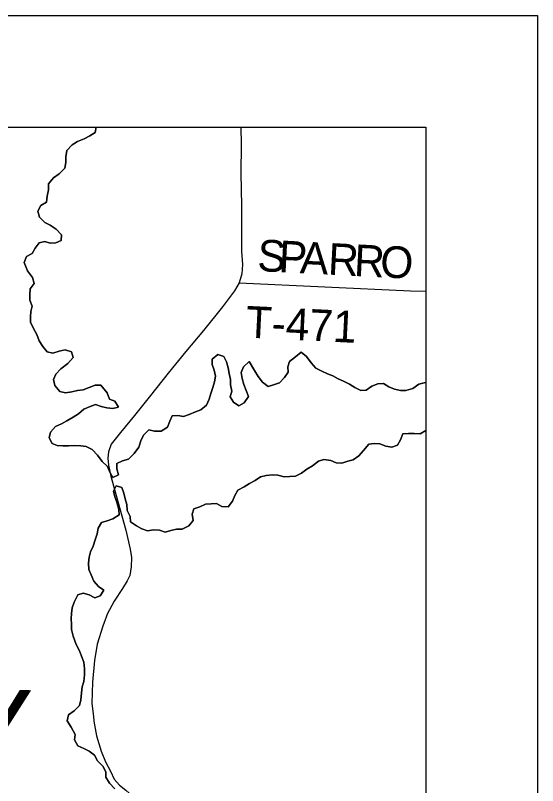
# Model space of a CAD drawing. Extents: x -22 to 431, y -18 to 160.
# Drawn here: x 331.059 to 331.995, y 158.739 to 160.12 of the extents above; entities that cross this region are included whole.
import ezdxf

# ---------------------------------------------------------------- set-up
doc = ezdxf.new("R2010")
doc.units = 0
for name, color, linetype in [('GM_X_City_Street_Text', 7, 'Continuous'), ('GM_X_County_ROW', 7, 'Continuous'), ('GM_X_Minor_River_Text', 7, 'Continuous'), ('GM_X_Section', 7, 'Continuous'), ('GM_X_Township_Subdivision', 7, 'Continuous'), ('GM_X_Unincorporated_Text', 7, 'Continuous')]:
    doc.layers.add(name, color=color, linetype=linetype)

msp = doc.modelspace()

# ---------------------------------------------------------------- linework, layer by layer
at = {"layer": 'GM_X_County_ROW'}
for points in [[(331.4632, 159.9199), (331.4635, 159.8894), (331.4632, 159.8358), (331.4637, 159.8092), (331.4637, 159.8092)], [(331.4637, 159.8092), (331.4642, 159.7777), (331.4646, 159.734), (331.4641, 159.6967), (331.4664, 159.6732), (331.4652, 159.6565), (331.4605, 159.6404), (331.452, 159.6262), (331.4305, 159.5974), (331.3963, 159.5554), (331.3647, 159.5176), (331.3331, 159.4784), (331.3012, 159.4387), (331.2726, 159.4029), (331.2477, 159.3725), (331.231, 159.3513), (331.2259, 159.3379), (331.2249, 159.3261), (331.2259, 159.3136), (331.2304, 159.2943), (331.243, 159.2489), (331.2571, 159.1971), (331.2649, 159.1634), (331.2671, 159.1483), (331.2666, 159.1315), (331.2642, 159.1159), (331.2598, 159.1064), (331.251, 159.0929), (331.2362, 159.0699), (331.224, 159.0469), (331.222, 159.0414)], [(331.222, 159.0414), (331.2185, 159.0317), (331.2161, 159.0251), (331.206, 158.9927), (331.2012, 158.9637), (331.1973, 158.9249), (331.1964, 158.8865), (331.1984, 158.868)], [(331.1984, 158.868), (331.1996, 158.8569), (331.1999, 158.855), (331.2046, 158.8285), (331.2131, 158.8009), (331.2206, 158.7821), (331.2296, 158.7651), (331.2363, 158.7508), (331.246, 158.74), (331.2571, 158.731), (331.2698, 158.72), (331.2794, 158.7119), (331.2882, 158.7011)]]:
    msp.add_lwpolyline(points, dxfattribs=at)
at = {"layer": 'GM_X_Minor_River_Text'}
msp.add_lwpolyline([(331.4605, 159.6404), (331.7672, 159.626), (331.7949, 159.6255)], dxfattribs=at)
at = {"layer": 'GM_X_Section'}
for p, q in [((319.5549, 159.9199), (331.7949, 159.9199)), ((331.7949, 159.9199), (331.7949, 147.6799))]:
    msp.add_line(p, q, dxfattribs=at)
msp.add_lwpolyline([(319.3549, 160.1199), (331.9949, 160.1199), (331.9949, 147.4799), (319.3549, 147.4799)], close=True, dxfattribs=at)
at = {"layer": 'GM_X_Township_Subdivision'}
for points in [[(331.131, 159.3833), (331.1419, 159.388), (331.1517, 159.393), (331.1626, 159.3996), (331.1724, 159.4058), (331.1821, 159.4139), (331.193, 159.4189), (331.2028, 159.4228), (331.2127, 159.4192), (331.2233, 159.4163), (331.2339, 159.4156), (331.2438, 159.418), (331.2376, 159.4282), (331.2281, 159.4323), (331.2238, 159.4432), (331.2123, 159.4571), (331.2025, 159.4573), (331.1912, 159.4527), (331.1806, 159.4491), (331.1708, 159.4475), (331.1602, 159.4451), (331.1489, 159.4434), (331.139, 159.4459), (331.1302, 159.4565), (331.1278, 159.4671), (331.1315, 159.4766), (331.1405, 159.4866), (331.1533, 159.4958), (331.1626, 159.5066), (331.1598, 159.5168), (331.1484, 159.5204), (331.1379, 159.5184), (331.1266, 159.5145), (331.1163, 159.517), (331.1083, 159.5267), (331.1021, 159.5369), (331.0978, 159.5482), (331.092, 159.5588), (331.0866, 159.5701), (331.0861, 159.5796), (331.0868, 159.5894), (331.0893, 159.599), (331.0854, 159.6095), (331.085, 159.6194), (331.086, 159.63), (331.0927, 159.6396), (331.0899, 159.6502), (331.0811, 159.6622), (331.0753, 159.6773), (331.0793, 159.6876), (331.0891, 159.693), (331.0947, 159.7026), (331.1017, 159.7122), (331.1123, 159.7146), (331.1218, 159.7116), (331.1316, 159.7121), (331.1414, 159.7164), (331.1417, 159.7267), (331.1321, 159.7368), (331.1214, 159.7439), (331.1119, 159.7487), (331.1024, 159.7581), (331.0996, 159.769), (331.1048, 159.779), (331.1153, 159.7852), (331.1164, 159.7958), (331.1185, 159.8072), (331.1184, 159.8178), (331.1273, 159.8289), (331.1375, 159.8359), (331.148, 159.8459), (331.1494, 159.8561), (331.1496, 159.8664), (331.1514, 159.8778), (331.1608, 159.8881), (331.1705, 159.894), (331.1826, 159.8987), (331.1924, 159.9041), (331.2021, 159.9099), (331.2043, 159.9198), (331.2043, 159.9199)], [(331.2043, 159.9199), (331.2043, 159.9198), (331.2021, 159.9099), (331.1924, 159.9041), (331.1826, 159.8987), (331.1705, 159.894), (331.1608, 159.8881), (331.1514, 159.8778), (331.1496, 159.8664), (331.1494, 159.8561), (331.148, 159.8459), (331.1375, 159.8359), (331.1273, 159.8289), (331.1184, 159.8178), (331.1185, 159.8072), (331.1164, 159.7958), (331.1153, 159.7852), (331.1048, 159.779), (331.0996, 159.769), (331.1024, 159.7581), (331.1119, 159.7487), (331.1214, 159.7439), (331.1321, 159.7368), (331.1417, 159.7267), (331.1414, 159.7164), (331.1316, 159.7121), (331.1218, 159.7116), (331.1123, 159.7146), (331.1017, 159.7122), (331.0947, 159.7026), (331.0891, 159.693), (331.0793, 159.6876), (331.0753, 159.6773), (331.0811, 159.6622), (331.0899, 159.6502), (331.0927, 159.6396), (331.086, 159.63), (331.085, 159.6194), (331.0854, 159.6095), (331.0893, 159.599), (331.0868, 159.5894), (331.0861, 159.5796), (331.0866, 159.5701), (331.092, 159.5588), (331.0978, 159.5482), (331.1021, 159.5369), (331.1083, 159.5267), (331.1163, 159.517), (331.1266, 159.5145), (331.1379, 159.5184), (331.1484, 159.5204), (331.1598, 159.5168), (331.1626, 159.5066), (331.1533, 159.4958), (331.1405, 159.4866), (331.1315, 159.4766), (331.1278, 159.4671), (331.1302, 159.4565), (331.139, 159.4459), (331.1489, 159.4434), (331.1602, 159.4451), (331.1708, 159.4475), (331.1806, 159.4491), (331.1912, 159.4527), (331.2025, 159.4573), (331.2123, 159.4571), (331.2238, 159.4432), (331.2281, 159.4323), (331.2376, 159.4282), (331.2438, 159.418), (331.2339, 159.4156), (331.2233, 159.4163), (331.2127, 159.4192), (331.2028, 159.4228), (331.193, 159.4189), (331.1821, 159.4139), (331.1724, 159.4058), (331.1626, 159.3996), (331.1517, 159.393), (331.1419, 159.388), (331.131, 159.3833)], [(331.7949, 159.4617), (331.7942, 159.462), (331.7821, 159.4588), (331.7712, 159.4514), (331.7591, 159.4479), (331.7493, 159.4478), (331.7387, 159.4503), (331.7284, 159.4539), (331.7185, 159.4599), (331.7087, 159.4594), (331.6981, 159.4555), (331.688, 159.4485), (331.6782, 159.4476), (331.6675, 159.4528), (331.658, 159.4591), (331.6473, 159.4643), (331.6378, 159.4684), (331.6279, 159.474), (331.6184, 159.4776), (331.6085, 159.4824), (331.5975, 159.4876), (331.5891, 159.4974), (331.581, 159.5083), (331.5711, 159.5165), (331.5614, 159.508), (331.5505, 159.4996), (331.5476, 159.49), (331.5477, 159.4806), (331.5417, 159.471), (331.5327, 159.4614), (331.5218, 159.4579), (331.512, 159.4547), (331.5021, 159.4625), (331.494, 159.4727), (331.4875, 159.4832), (331.4782, 159.4994), (331.4681, 159.4902), (331.464, 159.4799), (331.4653, 159.4693), (331.4684, 159.4583), (331.4727, 159.4474), (331.477, 159.4368), (331.4692, 159.4257), (331.4594, 159.4203), (331.4499, 159.4266), (331.4441, 159.4364), (331.447, 159.4467), (331.4446, 159.4577), (331.4445, 159.4672), (331.4425, 159.4781), (331.4405, 159.488), (331.4377, 159.4989), (331.4327, 159.5087), (331.4221, 159.5124), (331.4116, 159.5039), (331.4117, 159.4941), (331.4156, 159.4839), (331.418, 159.4733), (331.4162, 159.4634), (331.4133, 159.4527), (331.4092, 159.4421), (331.4063, 159.4318), (331.4019, 159.4215), (331.3917, 159.413), (331.3819, 159.4091), (331.3706, 159.4044), (331.3605, 159.4013), (331.3506, 159.4027), (331.3404, 159.4021), (331.336, 159.3926), (331.3319, 159.3819), (331.3206, 159.3746), (331.3085, 159.3748), (331.2983, 159.3774), (331.2886, 159.3678), (331.2838, 159.3575), (331.2805, 159.346), (331.2719, 159.3345), (331.2618, 159.3246), (331.2512, 159.3218), (331.2411, 159.3167), (331.2412, 159.3072), (331.2439, 159.2963), (331.2338, 159.2916), (331.2284, 159.3014), (331.2241, 159.3112), (331.2145, 159.3202), (331.2061, 159.3315), (331.1969, 159.3416), (331.1862, 159.3472), (331.1768, 159.3486), (331.1654, 159.3488), (331.1545, 159.3483), (331.1442, 159.3485), (331.1344, 159.3488), (331.1249, 159.3528), (331.1199, 159.3626), (331.1224, 159.3729), (331.131, 159.3833)], [(331.131, 159.3833), (331.1224, 159.3729), (331.1199, 159.3626), (331.1249, 159.3528), (331.1344, 159.3488), (331.1442, 159.3485), (331.1545, 159.3483), (331.1654, 159.3488), (331.1768, 159.3486), (331.1862, 159.3472), (331.1969, 159.3416), (331.2061, 159.3315), (331.2145, 159.3202), (331.2241, 159.3112), (331.2284, 159.3014), (331.2338, 159.2916), (331.2439, 159.2963), (331.2412, 159.3072), (331.2411, 159.3167), (331.2512, 159.3218), (331.2618, 159.3246), (331.2719, 159.3345), (331.2805, 159.346), (331.2838, 159.3575), (331.2886, 159.3678), (331.2983, 159.3774), (331.3085, 159.3748), (331.3206, 159.3746), (331.3319, 159.3819), (331.336, 159.3926), (331.3404, 159.4021), (331.3506, 159.4027), (331.3605, 159.4013), (331.3706, 159.4044), (331.3819, 159.4091), (331.3917, 159.413), (331.4019, 159.4215), (331.4063, 159.4318), (331.4092, 159.4421), (331.4133, 159.4527), (331.4162, 159.4634), (331.418, 159.4733), (331.4156, 159.4839), (331.4117, 159.4941), (331.4116, 159.5039), (331.4221, 159.5124), (331.4327, 159.5087), (331.4377, 159.4989), (331.4405, 159.488), (331.4425, 159.4781), (331.4445, 159.4672), (331.4446, 159.4577), (331.447, 159.4467), (331.4441, 159.4364), (331.4499, 159.4266), (331.4594, 159.4203), (331.4692, 159.4257), (331.477, 159.4368), (331.4727, 159.4474), (331.4684, 159.4583), (331.4653, 159.4693), (331.464, 159.4799), (331.4681, 159.4902), (331.4782, 159.4994), (331.4875, 159.4832), (331.494, 159.4727), (331.5021, 159.4625), (331.512, 159.4547), (331.5218, 159.4579), (331.5327, 159.4614), (331.5417, 159.471), (331.5477, 159.4806), (331.5476, 159.49), (331.5505, 159.4996), (331.5614, 159.508), (331.5711, 159.5165), (331.581, 159.5083), (331.5891, 159.4974), (331.5975, 159.4876), (331.6085, 159.4824), (331.6184, 159.4776), (331.6279, 159.474), (331.6378, 159.4684), (331.6473, 159.4643), (331.658, 159.4591), (331.6675, 159.4528), (331.6782, 159.4476), (331.688, 159.4485), (331.6981, 159.4555), (331.7087, 159.4594), (331.7185, 159.4599), (331.7284, 159.4539), (331.7387, 159.4503), (331.7493, 159.4478), (331.7591, 159.4479), (331.7712, 159.4514), (331.7821, 159.4588), (331.7942, 159.462), (331.7949, 159.4617)], [(331.1914, 159.0813), (331.2016, 159.0758), (331.2114, 159.0797), (331.2178, 159.0896), (331.2079, 159.0963), (331.1998, 159.1061), (331.1951, 159.117), (331.1909, 159.1268), (331.1904, 159.1382), (331.1914, 159.1488), (331.1936, 159.1584), (331.1984, 159.1687), (331.2024, 159.1801), (331.2057, 159.1907), (331.2075, 159.2006), (331.2138, 159.2113), (331.224, 159.2141), (331.2338, 159.2173), (331.2451, 159.225), (331.2446, 159.2345), (331.241, 159.2473), (331.2372, 159.2571), (331.2352, 159.267), (331.24, 159.2765), (331.2502, 159.2736), (331.2537, 159.2634), (331.2561, 159.2536), (331.2589, 159.243), (331.2597, 159.2324), (331.2652, 159.2218), (331.2656, 159.212), (331.2763, 159.2053), (331.2858, 159.1997), (331.2961, 159.196), (331.3067, 159.1981), (331.3176, 159.197), (331.3275, 159.1934), (331.3377, 159.1969), (331.3479, 159.1989), (331.3581, 159.1991), (331.3698, 159.2049), (331.3776, 159.2145), (331.376, 159.2258), (331.3789, 159.2357), (331.3898, 159.2393), (331.4, 159.2436), (331.4098, 159.2444), (331.4197, 159.2449), (331.4292, 159.2398), (331.4405, 159.2388), (331.4484, 159.2491), (331.4524, 159.2594), (331.458, 159.2689), (331.4693, 159.2748), (331.479, 159.281), (331.4888, 159.2864), (331.4986, 159.2929), (331.5084, 159.295), (331.5197, 159.2962), (331.5296, 159.2956), (331.541, 159.2931), (331.5614, 159.2941), (331.5716, 159.2992), (331.5817, 159.3069), (331.5918, 159.3127), (331.6023, 159.3208), (331.6121, 159.3239), (331.6243, 159.3222), (331.6342, 159.3177), (331.6444, 159.3175), (331.6549, 159.3207), (331.6647, 159.3234), (331.6749, 159.3308), (331.6827, 159.3403), (331.6924, 159.3515), (331.7023, 159.3527), (331.7121, 159.3521), (331.7227, 159.3477), (331.7337, 159.3459), (331.7439, 159.3494), (331.7495, 159.3594), (331.7535, 159.3697), (331.7637, 159.3705), (331.774, 159.3707), (331.7846, 159.37), (331.7949, 159.3757)], [(331.7949, 159.3757), (331.7846, 159.37), (331.774, 159.3707), (331.7637, 159.3705), (331.7535, 159.3697), (331.7495, 159.3594), (331.7439, 159.3494), (331.7337, 159.3459), (331.7227, 159.3477), (331.7121, 159.3521), (331.7023, 159.3527), (331.6924, 159.3515), (331.6827, 159.3403), (331.6749, 159.3308), (331.6647, 159.3234), (331.6549, 159.3207), (331.6444, 159.3175), (331.6342, 159.3177), (331.6243, 159.3222), (331.6121, 159.3239), (331.6023, 159.3208), (331.5918, 159.3127), (331.5817, 159.3069), (331.5716, 159.2992), (331.5614, 159.2941), (331.541, 159.2931), (331.5296, 159.2956), (331.5197, 159.2962), (331.5084, 159.295), (331.4986, 159.2929), (331.4888, 159.2864), (331.479, 159.281), (331.4693, 159.2748), (331.458, 159.2689), (331.4524, 159.2594), (331.4484, 159.2491), (331.4405, 159.2388), (331.4292, 159.2398), (331.4197, 159.2449), (331.4098, 159.2444), (331.4, 159.2436), (331.3898, 159.2393), (331.3789, 159.2357), (331.376, 159.2258), (331.3776, 159.2145), (331.3698, 159.2049), (331.3581, 159.1991), (331.3479, 159.1989), (331.3377, 159.1969), (331.3275, 159.1934), (331.3176, 159.197), (331.3067, 159.1981), (331.2961, 159.196), (331.2858, 159.1997), (331.2763, 159.2053), (331.2656, 159.212), (331.2652, 159.2218), (331.2597, 159.2324), (331.2589, 159.243), (331.2561, 159.2536), (331.2537, 159.2634), (331.2502, 159.2736), (331.24, 159.2765), (331.2352, 159.267), (331.2372, 159.2571), (331.241, 159.2473), (331.2446, 159.2345), (331.2451, 159.225), (331.2338, 159.2173), (331.224, 159.2141), (331.2138, 159.2113), (331.2075, 159.2006), (331.2057, 159.1907), (331.2024, 159.1801), (331.1984, 159.1687), (331.1936, 159.1584), (331.1914, 159.1488), (331.1904, 159.1382), (331.1909, 159.1268), (331.1951, 159.117), (331.1998, 159.1061), (331.2079, 159.0963), (331.2178, 159.0896), (331.2114, 159.0797), (331.2016, 159.0758), (331.1914, 159.0813)], [(331.2374, 158.7334), (331.2279, 158.7439), (331.2213, 158.7548), (331.2212, 158.7643), (331.2158, 158.7745), (331.2063, 158.7838), (331.2012, 158.794), (331.1913, 158.8011), (331.1818, 158.8059), (331.1712, 158.8107), (331.1654, 158.8213), (331.1664, 158.8308), (331.1591, 158.8439), (331.1518, 158.8556), (331.1547, 158.8663), (331.1644, 158.8736), (331.1742, 158.8832), (331.1763, 158.8934), (331.1777, 158.906), (331.1787, 158.9166), (331.182, 158.9261), (331.1834, 158.9379), (331.1829, 158.9489), (331.1817, 158.9606), (331.1778, 158.9712), (331.1739, 158.981), (331.1681, 158.9923), (331.1626, 159.007), (331.1599, 159.0191), (331.1598, 159.029), (331.1593, 159.0385), (331.1599, 159.048), (331.1613, 159.0582), (331.1646, 159.0685), (331.1709, 159.0815), (331.1807, 159.0846), (331.1914, 159.0813)], [(331.1914, 159.0813), (331.1807, 159.0846), (331.1709, 159.0815), (331.1646, 159.0685), (331.1613, 159.0582), (331.1599, 159.048), (331.1593, 159.0385), (331.1598, 159.029), (331.1599, 159.0191), (331.1626, 159.007), (331.1681, 158.9923), (331.1739, 158.981), (331.1778, 158.9712), (331.1817, 158.9606), (331.1829, 158.9489), (331.1834, 158.9379), (331.182, 158.9261), (331.1787, 158.9166), (331.1777, 158.906), (331.1763, 158.8934), (331.1742, 158.8832), (331.1644, 158.8736), (331.1547, 158.8663), (331.1518, 158.8556), (331.1591, 158.8439), (331.1664, 158.8308), (331.1654, 158.8213), (331.1712, 158.8107), (331.1818, 158.8059), (331.1913, 158.8011), (331.2012, 158.794), (331.2063, 158.7838), (331.2158, 158.7745), (331.2212, 158.7643), (331.2213, 158.7548), (331.2279, 158.7439), (331.2374, 158.7334)]]:
    msp.add_lwpolyline(points, dxfattribs=at)

# ---------------------------------------------------------------- texts
at = {"layer": 'GM_X_City_Street_Text'}
for s, height, rotation, p in [('S', 0.0568, 357.0695, (331.4919, 159.6619)), ('P', 0.0568, 357.0671, (331.5301, 159.6599)), ('A', 0.0568, 357.0708, (331.5684, 159.658)), ('R', 0.0568, 357.0676, (331.6184, 159.6554)), ('R', 0.0568, 357.0719, (331.665, 159.653)), ('O', 0.0568, 357.4292, (331.712, 159.6506)), ('T-471', 0.05682, 357.1936, (331.4709, 159.5426))]:
    msp.add_text(s, height=height, rotation=rotation, dxfattribs=at).set_placement(p)
at = {"layer": 'GM_X_Unincorporated_Text'}
msp.add_text('GUERNSEY COUNTY', height=0.15, rotation=358.733, dxfattribs=at).set_placement((329.0609, 158.8052))

doc.saveas('drawing.dxf')
